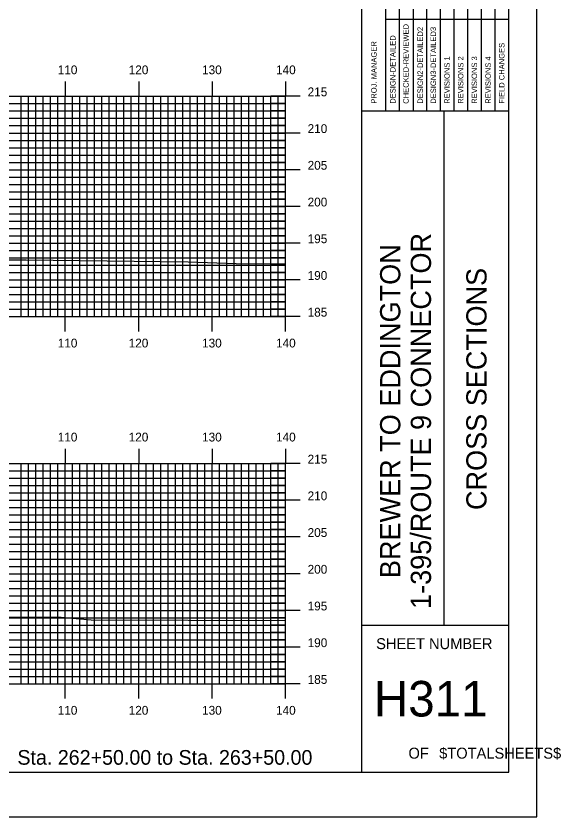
# Model space of a CAD drawing. Extents: x 1806651 to 1806995, y 442591 to 442811.
# Drawn here: x 1806920.6 to 1806994.7, y 442590.5 to 442699.6 of the extents above; entities that cross this region are included whole.
import ezdxf

# ---------------------------------------------------------------- set-up
doc = ezdxf.new("R2010")
doc.units = 0
for name, color, linetype in [('BORDER', 7, 'Continuous'), ('H_V ANNOTATION', 7, 'Continuous'), ('MAJOR', 7, 'Continuous'), ('MINOR', 7, 'Continuous'), ('PLOT BOUNDARY', 7, 'Continuous'), ('S_Roadway_Centerline', 7, 'Continuous')]:
    doc.layers.add(name, color=color, linetype=linetype)

msp = doc.modelspace()

# ---------------------------------------------------------------- linework, layer by layer
at = {"layer": 'BORDER'}
for p, q in [((1806967.65, 442596.67), (1806967.65, 442806.67)), ((1806967.65, 442686.67), (1806987.65, 442686.67)), ((1806978.83, 442616.67), (1806978.83, 442686.67)), ((1806967.65, 442616.67), (1806987.65, 442616.67))]:
    msp.add_line(p, q, dxfattribs=at)
msp.add_lwpolyline([(1806667.65, 442596.67), (1806987.65, 442596.67), (1806987.65, 442806.67), (1806667.65, 442806.67)], close=True, dxfattribs=at)
for points in [[(1806972.74, 442686.68), (1806972.74, 442721.67)], [(1806974.6, 442721.67), (1806974.6, 442686.68)], [(1806976.47, 442686.68), (1806976.47, 442721.67)], [(1806978.33, 442686.68), (1806978.33, 442721.67)], [(1806980.19, 442686.68), (1806980.19, 442721.67)], [(1806982.06, 442686.68), (1806982.06, 442721.67)], [(1806983.92, 442686.68), (1806983.92, 442721.67)], [(1806985.78, 442686.68), (1806985.78, 442721.67)], [(1806970.88, 442686.68), (1806970.88, 442720.26)], [(1806970.88, 442699.17), (1806987.65, 442699.17)]]:
    msp.add_lwpolyline(points, dxfattribs=at)
at = {"layer": 'MAJOR'}
for p, q in [((1806927.25, 442690.67), (1806927.25, 442688.67)), ((1806937.25, 442690.67), (1806937.25, 442688.67)), ((1806947.25, 442690.67), (1806947.25, 442688.67)), ((1806957.25, 442690.67), (1806957.25, 442688.67)), ((1806677.25, 442688.67), (1806957.25, 442688.67)), ((1806677.25, 442688.67), (1806957.25, 442688.67)), ((1806927.25, 442658.67), (1806927.25, 442688.67)), ((1806937.25, 442658.67), (1806937.25, 442688.67)), ((1806947.25, 442658.67), (1806947.25, 442688.67)), ((1806959.25, 442688.67), (1806955.24, 442688.67)), ((1806957.25, 442658.67), (1806957.25, 442688.67)), ((1806957.25, 442658.67), (1806957.25, 442688.67)), ((1806677.25, 442683.67), (1806957.25, 442683.67)), ((1806959.25, 442683.67), (1806955.24, 442683.67)), ((1806677.25, 442678.67), (1806957.25, 442678.67)), ((1806959.25, 442678.67), (1806955.24, 442678.67)), ((1806677.25, 442673.67), (1806957.25, 442673.67)), ((1806959.25, 442673.67), (1806955.24, 442673.67)), ((1806677.25, 442668.67), (1806957.25, 442668.67)), ((1806959.25, 442668.67), (1806955.24, 442668.67)), ((1806677.25, 442663.67), (1806957.25, 442663.67)), ((1806959.25, 442663.67), (1806955.24, 442663.67)), ((1806677.25, 442658.67), (1806957.25, 442658.67)), ((1806677.25, 442658.67), (1806957.25, 442658.67)), ((1806927.25, 442656.66), (1806927.25, 442658.67)), ((1806937.25, 442656.66), (1806937.25, 442658.67)), ((1806947.25, 442656.66), (1806947.25, 442658.67)), ((1806959.25, 442658.67), (1806955.24, 442658.67)), ((1806957.25, 442656.66), (1806957.25, 442658.67)), ((1806927.25, 442640.67), (1806927.25, 442638.67)), ((1806937.25, 442640.67), (1806937.25, 442638.67)), ((1806947.25, 442640.67), (1806947.25, 442638.67)), ((1806957.25, 442640.67), (1806957.25, 442638.67)), ((1806677.25, 442638.67), (1806957.25, 442638.67)), ((1806677.25, 442638.67), (1806957.25, 442638.67)), ((1806927.25, 442608.67), (1806927.25, 442638.67)), ((1806937.25, 442608.67), (1806937.25, 442638.67)), ((1806947.25, 442608.67), (1806947.25, 442638.67)), ((1806959.25, 442638.67), (1806955.24, 442638.67)), ((1806957.25, 442608.67), (1806957.25, 442638.67)), ((1806957.25, 442608.67), (1806957.25, 442638.67)), ((1806677.25, 442633.67), (1806957.25, 442633.67)), ((1806959.25, 442633.67), (1806955.24, 442633.67)), ((1806677.25, 442628.67), (1806957.25, 442628.67)), ((1806959.25, 442628.67), (1806955.24, 442628.67)), ((1806677.25, 442623.67), (1806957.25, 442623.67)), ((1806959.25, 442623.67), (1806955.24, 442623.67)), ((1806677.25, 442618.67), (1806957.25, 442618.67)), ((1806959.25, 442618.67), (1806955.24, 442618.67)), ((1806677.25, 442613.67), (1806957.25, 442613.67)), ((1806959.25, 442613.67), (1806955.24, 442613.67)), ((1806677.25, 442608.67), (1806957.25, 442608.67)), ((1806677.25, 442608.67), (1806957.25, 442608.67)), ((1806927.25, 442606.66), (1806927.25, 442608.67)), ((1806937.25, 442606.66), (1806937.25, 442608.67)), ((1806947.25, 442606.66), (1806947.25, 442608.67)), ((1806959.25, 442608.67), (1806955.24, 442608.67)), ((1806957.25, 442606.66), (1806957.25, 442608.67))]:
    msp.add_line(p, q, dxfattribs=at)
at = {"layer": 'MINOR'}
for p, q in [((1806921.25, 442658.67), (1806921.25, 442688.67)), ((1806922.25, 442658.67), (1806922.25, 442688.67)), ((1806923.25, 442658.67), (1806923.25, 442688.67)), ((1806924.25, 442658.67), (1806924.25, 442688.67)), ((1806925.25, 442658.67), (1806925.25, 442688.67)), ((1806926.25, 442658.67), (1806926.25, 442688.67)), ((1806928.25, 442658.67), (1806928.25, 442688.67)), ((1806929.25, 442658.67), (1806929.25, 442688.67)), ((1806930.25, 442658.67), (1806930.25, 442688.67)), ((1806931.25, 442658.67), (1806931.25, 442688.67)), ((1806932.25, 442658.67), (1806932.25, 442688.67)), ((1806933.25, 442658.67), (1806933.25, 442688.67)), ((1806934.25, 442658.67), (1806934.25, 442688.67)), ((1806935.25, 442658.67), (1806935.25, 442688.67)), ((1806936.25, 442658.67), (1806936.25, 442688.67)), ((1806938.25, 442658.67), (1806938.25, 442688.67)), ((1806939.25, 442658.67), (1806939.25, 442688.67)), ((1806940.25, 442658.67), (1806940.25, 442688.67)), ((1806941.25, 442658.67), (1806941.25, 442688.67)), ((1806942.25, 442658.67), (1806942.25, 442688.67)), ((1806943.25, 442658.67), (1806943.25, 442688.67)), ((1806944.25, 442658.67), (1806944.25, 442688.67)), ((1806945.25, 442658.67), (1806945.25, 442688.67)), ((1806946.25, 442658.67), (1806946.25, 442688.67)), ((1806948.25, 442658.67), (1806948.25, 442688.67)), ((1806949.25, 442658.67), (1806949.25, 442688.67)), ((1806950.25, 442658.67), (1806950.25, 442688.67)), ((1806951.25, 442658.67), (1806951.25, 442688.67)), ((1806952.25, 442658.67), (1806952.25, 442688.67)), ((1806953.25, 442658.67), (1806953.25, 442688.67)), ((1806954.25, 442658.67), (1806954.25, 442688.67)), ((1806955.25, 442658.67), (1806955.25, 442688.67)), ((1806956.25, 442658.67), (1806956.25, 442688.67)), ((1806677.25, 442687.67), (1806957.25, 442687.67)), ((1806957.25, 442687.67), (1806955.24, 442687.67)), ((1806677.25, 442686.67), (1806957.25, 442686.67)), ((1806957.25, 442686.67), (1806955.24, 442686.67)), ((1806677.25, 442685.67), (1806957.25, 442685.67)), ((1806957.25, 442685.67), (1806955.24, 442685.67)), ((1806677.25, 442684.67), (1806957.25, 442684.67)), ((1806957.25, 442684.67), (1806955.24, 442684.67)), ((1806677.25, 442682.67), (1806957.25, 442682.67)), ((1806957.25, 442682.67), (1806955.24, 442682.67)), ((1806677.25, 442681.67), (1806957.25, 442681.67)), ((1806957.25, 442681.67), (1806955.24, 442681.67)), ((1806677.25, 442680.67), (1806957.25, 442680.67)), ((1806677.25, 442679.67), (1806957.25, 442679.67)), ((1806957.25, 442680.67), (1806955.24, 442680.67)), ((1806957.25, 442679.67), (1806955.24, 442679.67)), ((1806677.25, 442677.67), (1806957.25, 442677.67)), ((1806957.25, 442677.67), (1806955.24, 442677.67)), ((1806677.25, 442676.67), (1806957.25, 442676.67)), ((1806957.25, 442676.67), (1806955.24, 442676.67)), ((1806677.25, 442675.67), (1806957.25, 442675.67)), ((1806957.25, 442675.67), (1806955.24, 442675.67)), ((1806677.25, 442674.67), (1806957.25, 442674.67)), ((1806957.25, 442674.67), (1806955.24, 442674.67)), ((1806677.25, 442672.67), (1806957.25, 442672.67)), ((1806957.25, 442672.67), (1806955.24, 442672.67)), ((1806677.25, 442671.67), (1806957.25, 442671.67)), ((1806957.25, 442671.67), (1806955.24, 442671.67)), ((1806677.25, 442670.67), (1806957.25, 442670.67)), ((1806957.25, 442670.67), (1806955.24, 442670.67)), ((1806677.25, 442669.67), (1806957.25, 442669.67)), ((1806957.25, 442669.67), (1806955.24, 442669.67)), ((1806677.25, 442667.67), (1806957.25, 442667.67)), ((1806957.25, 442667.67), (1806955.24, 442667.67)), ((1806677.25, 442666.67), (1806957.25, 442666.67)), ((1806957.25, 442666.67), (1806955.24, 442666.67)), ((1806677.25, 442665.67), (1806957.25, 442665.67)), ((1806957.25, 442665.67), (1806955.24, 442665.67)), ((1806677.25, 442664.67), (1806957.25, 442664.67)), ((1806957.25, 442664.67), (1806955.24, 442664.67)), ((1806677.25, 442662.67), (1806957.25, 442662.67)), ((1806957.25, 442662.67), (1806955.24, 442662.67)), ((1806677.25, 442661.67), (1806957.25, 442661.67)), ((1806957.25, 442661.67), (1806955.24, 442661.67)), ((1806677.25, 442660.67), (1806957.25, 442660.67)), ((1806957.25, 442660.67), (1806955.24, 442660.67)), ((1806677.25, 442659.67), (1806957.25, 442659.67)), ((1806957.25, 442659.67), (1806955.24, 442659.67)), ((1806921.25, 442608.67), (1806921.25, 442638.67)), ((1806922.25, 442608.67), (1806922.25, 442638.67)), ((1806923.25, 442608.67), (1806923.25, 442638.67)), ((1806924.25, 442608.67), (1806924.25, 442638.67)), ((1806925.25, 442608.67), (1806925.25, 442638.67)), ((1806926.25, 442608.67), (1806926.25, 442638.67)), ((1806928.25, 442608.67), (1806928.25, 442638.67)), ((1806929.25, 442608.67), (1806929.25, 442638.67)), ((1806930.25, 442608.67), (1806930.25, 442638.67)), ((1806931.25, 442608.67), (1806931.25, 442638.67)), ((1806932.25, 442608.67), (1806932.25, 442638.67)), ((1806933.25, 442608.67), (1806933.25, 442638.67)), ((1806934.25, 442608.67), (1806934.25, 442638.67)), ((1806935.25, 442608.67), (1806935.25, 442638.67)), ((1806936.25, 442608.67), (1806936.25, 442638.67)), ((1806938.25, 442608.67), (1806938.25, 442638.67)), ((1806939.25, 442608.67), (1806939.25, 442638.67)), ((1806940.25, 442608.67), (1806940.25, 442638.67)), ((1806941.25, 442608.67), (1806941.25, 442638.67)), ((1806942.25, 442608.67), (1806942.25, 442638.67)), ((1806943.25, 442608.67), (1806943.25, 442638.67)), ((1806944.25, 442608.67), (1806944.25, 442638.67)), ((1806945.25, 442608.67), (1806945.25, 442638.67)), ((1806946.25, 442608.67), (1806946.25, 442638.67)), ((1806948.25, 442608.67), (1806948.25, 442638.67)), ((1806949.25, 442608.67), (1806949.25, 442638.67)), ((1806950.25, 442608.67), (1806950.25, 442638.67)), ((1806951.25, 442608.67), (1806951.25, 442638.67)), ((1806952.25, 442608.67), (1806952.25, 442638.67)), ((1806953.25, 442608.67), (1806953.25, 442638.67)), ((1806954.25, 442608.67), (1806954.25, 442638.67)), ((1806955.25, 442608.67), (1806955.25, 442638.67)), ((1806956.25, 442608.67), (1806956.25, 442638.67)), ((1806677.25, 442637.67), (1806957.25, 442637.67)), ((1806957.25, 442637.67), (1806955.24, 442637.67)), ((1806677.25, 442636.67), (1806957.25, 442636.67)), ((1806957.25, 442636.67), (1806955.24, 442636.67)), ((1806677.25, 442635.67), (1806957.25, 442635.67)), ((1806957.25, 442635.67), (1806955.24, 442635.67)), ((1806677.25, 442634.67), (1806957.25, 442634.67)), ((1806957.25, 442634.67), (1806955.24, 442634.67)), ((1806677.25, 442632.67), (1806957.25, 442632.67)), ((1806957.25, 442632.67), (1806955.24, 442632.67)), ((1806677.25, 442631.67), (1806957.25, 442631.67)), ((1806677.25, 442630.67), (1806957.25, 442630.67)), ((1806957.25, 442631.67), (1806955.24, 442631.67)), ((1806957.25, 442630.67), (1806955.24, 442630.67)), ((1806677.25, 442629.67), (1806957.25, 442629.67)), ((1806957.25, 442629.67), (1806955.24, 442629.67)), ((1806677.25, 442627.67), (1806957.25, 442627.67)), ((1806957.25, 442627.67), (1806955.24, 442627.67)), ((1806677.25, 442626.67), (1806957.25, 442626.67)), ((1806957.25, 442626.67), (1806955.24, 442626.67)), ((1806677.25, 442625.67), (1806957.25, 442625.67)), ((1806957.25, 442625.67), (1806955.24, 442625.67)), ((1806677.25, 442624.67), (1806957.25, 442624.67)), ((1806957.25, 442624.67), (1806955.24, 442624.67)), ((1806677.25, 442622.67), (1806957.25, 442622.67)), ((1806957.25, 442622.67), (1806955.24, 442622.67)), ((1806677.25, 442621.67), (1806957.25, 442621.67)), ((1806957.25, 442621.67), (1806955.24, 442621.67)), ((1806677.25, 442620.67), (1806957.25, 442620.67)), ((1806957.25, 442620.67), (1806955.24, 442620.67)), ((1806677.25, 442619.67), (1806957.25, 442619.67)), ((1806957.25, 442619.67), (1806955.24, 442619.67)), ((1806677.25, 442617.67), (1806957.25, 442617.67)), ((1806957.25, 442617.67), (1806955.24, 442617.67)), ((1806677.25, 442616.67), (1806957.25, 442616.67)), ((1806957.25, 442616.67), (1806955.24, 442616.67)), ((1806677.25, 442615.67), (1806957.25, 442615.67)), ((1806957.25, 442615.67), (1806955.24, 442615.67)), ((1806677.25, 442614.67), (1806957.25, 442614.67)), ((1806957.25, 442614.67), (1806955.24, 442614.67)), ((1806677.25, 442612.67), (1806957.25, 442612.67)), ((1806957.25, 442612.67), (1806955.24, 442612.67)), ((1806677.25, 442611.67), (1806957.25, 442611.67)), ((1806957.25, 442611.67), (1806955.24, 442611.67)), ((1806677.25, 442610.67), (1806957.25, 442610.67)), ((1806957.25, 442610.67), (1806955.24, 442610.67)), ((1806677.25, 442609.67), (1806957.25, 442609.67)), ((1806957.25, 442609.67), (1806955.24, 442609.67))]:
    msp.add_line(p, q, dxfattribs=at)
at = {"layer": 'PLOT BOUNDARY'}
msp.add_lwpolyline([(1806651.46, 442590.55), (1806991.46, 442590.55), (1806991.46, 442810.55), (1806651.46, 442810.55)], close=True, dxfattribs=at)
at = {"layer": 'S_Roadway_Centerline'}
for points in [[(1806821.89, 442667.95), (1806856.56, 442667.51), (1806870.7, 442667.4), (1806873.25, 442667.39), (1806891.61, 442666.72), (1806894.85, 442666.6), (1806895.82, 442666.57), (1806917, 442666.38), (1806919.2, 442666.38), (1806921.92, 442666.4), (1806944.01, 442666.14), (1806950.5, 442665.91), (1806955.14, 442665.87), (1806957.25, 442665.89)], [(1806835.26, 442618.46), (1806853.24, 442618.41), (1806854.41, 442618.41), (1806854.59, 442618.41), (1806888.04, 442617.66), (1806891.49, 442617.57), (1806894.18, 442617.58), (1806913.19, 442617.71), (1806915.76, 442617.74), (1806926.18, 442617.8), (1806930.78, 442617.41), (1806957.25, 442617.28)]]:
    msp.add_lwpolyline(points, dxfattribs=at)

# ---------------------------------------------------------------- texts
at = {"layer": 'BORDER'}
for s, height, p in [('CHECKED-REVIEWED', 0.7455, (1806974.01, 442687.65)), ('DESIGN2-DETAILED2', 0.7455, (1806975.95, 442687.65)), ('DESIGN3-DETAILED3', 0.7455, (1806977.73, 442687.65)), ('DESIGN-DETAILED', 0.7455, (1806972.22, 442687.65)), ('PROJ. MANAGER', 0.7455, (1806969.65, 442687.65)), ('FIELD CHANGES', 0.7455, (1806987.05, 442687.65)), ('REVISIONS 1', 0.7455, (1806979.6, 442687.65)), ('REVISIONS 2', 0.7455, (1806981.46, 442687.65)), ('REVISIONS 3', 0.7455, (1806983.32, 442687.65)), ('REVISIONS 4', 0.7455, (1806985.19, 442687.65)), ('1-395/ROUTE 9 CONNECTOR', 2.7557, (1806977.05, 442618.87)), ('BREWER TO EDDINGTON', 2.7557, (1806972.87, 442623.07)), ('CROSS SECTIONS', 2.7557, (1806984.61, 442632.34))]:
    msp.add_text(s, height=height, rotation=90, dxfattribs=at).set_placement(p)
for s, height, p in [('SHEET NUMBER', 1.4905, (1806969.58, 442613.4)), ('H311', 4.839, (1806969.27, 442604.23)), ('$TOTALSHEETS$', 1.4905, (1806978.16, 442598.49)), ('OF', 1.491, (1806973.98, 442598.49))]:
    msp.add_text(s, height=height, dxfattribs=at).set_placement(p)
at = {"layer": 'H_V ANNOTATION'}
for s, height, p in [('110', 1.2, (1806926.23, 442691.67)), ('120', 1.2, (1806935.89, 442691.67)), ('130', 1.2, (1806945.88, 442691.67)), ('140', 1.2, (1806955.95, 442691.67)), ('215', 1.2, (1806960.25, 442688.67)), ('210', 1.2, (1806960.25, 442683.67)), ('205', 1.2, (1806960.25, 442678.67)), ('200', 1.2, (1806960.25, 442673.67)), ('195', 1.2, (1806960.25, 442668.67)), ('190', 1.2, (1806960.25, 442663.67)), ('185', 1.2, (1806960.25, 442658.67)), ('110', 1.2, (1806926.23, 442654.47)), ('120', 1.2, (1806935.89, 442654.47)), ('130', 1.2, (1806945.88, 442654.47)), ('140', 1.2, (1806955.95, 442654.47)), ('110', 1.2, (1806926.23, 442641.67)), ('120', 1.2, (1806935.89, 442641.67)), ('130', 1.2, (1806945.88, 442641.67)), ('140', 1.2, (1806955.95, 442641.67)), ('215', 1.2, (1806960.25, 442638.67)), ('210', 1.2, (1806960.25, 442633.67)), ('205', 1.2, (1806960.25, 442628.67)), ('200', 1.2, (1806960.25, 442623.67)), ('195', 1.2, (1806960.25, 442618.67)), ('190', 1.2, (1806960.25, 442613.67)), ('185', 1.2, (1806960.25, 442608.67)), ('110', 1.2, (1806926.23, 442604.47)), ('120', 1.2, (1806935.89, 442604.47)), ('130', 1.2, (1806945.88, 442604.47)), ('140', 1.2, (1806955.95, 442604.47)), ('Sta. 262+50.00 to Sta. 263+50.00', 2.0004, (1806920.74, 442597.66))]:
    msp.add_text(s, height=height, dxfattribs=at).set_placement(p)

doc.saveas('drawing.dxf')
